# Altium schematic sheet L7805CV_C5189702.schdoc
size 127 x 101 mm
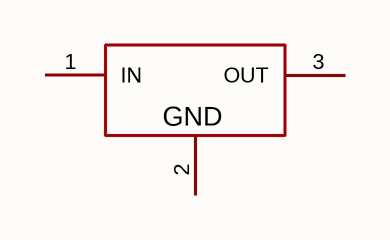
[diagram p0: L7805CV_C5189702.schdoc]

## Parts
U?  l7805cv_c5189702  [TO-220-3_L10.0-W4.5-P2.54-L]  (value not drawn)

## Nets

Not connected (* = marked no-connect by the designer): U? 1(IN) 2(GND) 3(OUT)

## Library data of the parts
U? = l7805cv_c5189702: 输出极性:正极;工作电压:20V;输出电压:5V;输出电流:1.2A;电源纹波抑制比(PSRR):-;输出类型:固定;; Manufacturer: JSMSEMI(杰盛微); AddInBom: yes; ModelId: b3c9e38e4428458f8b925050989b538f; ModelTransform: 401.574,178.58232,0,0,0,0,0,25.59,-196.85; Output Configuration: 正极; Voltage - Supply: 20V; Output Voltage: 5V; Output Current: 1.2A; standby current: 6mA; Output Type: 固定; Number of Outputs: 1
